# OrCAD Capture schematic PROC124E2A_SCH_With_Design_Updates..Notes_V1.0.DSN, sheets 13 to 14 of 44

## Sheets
13 09. USB TYPE-C POWER: size C; title: USB TYPE-C POWER
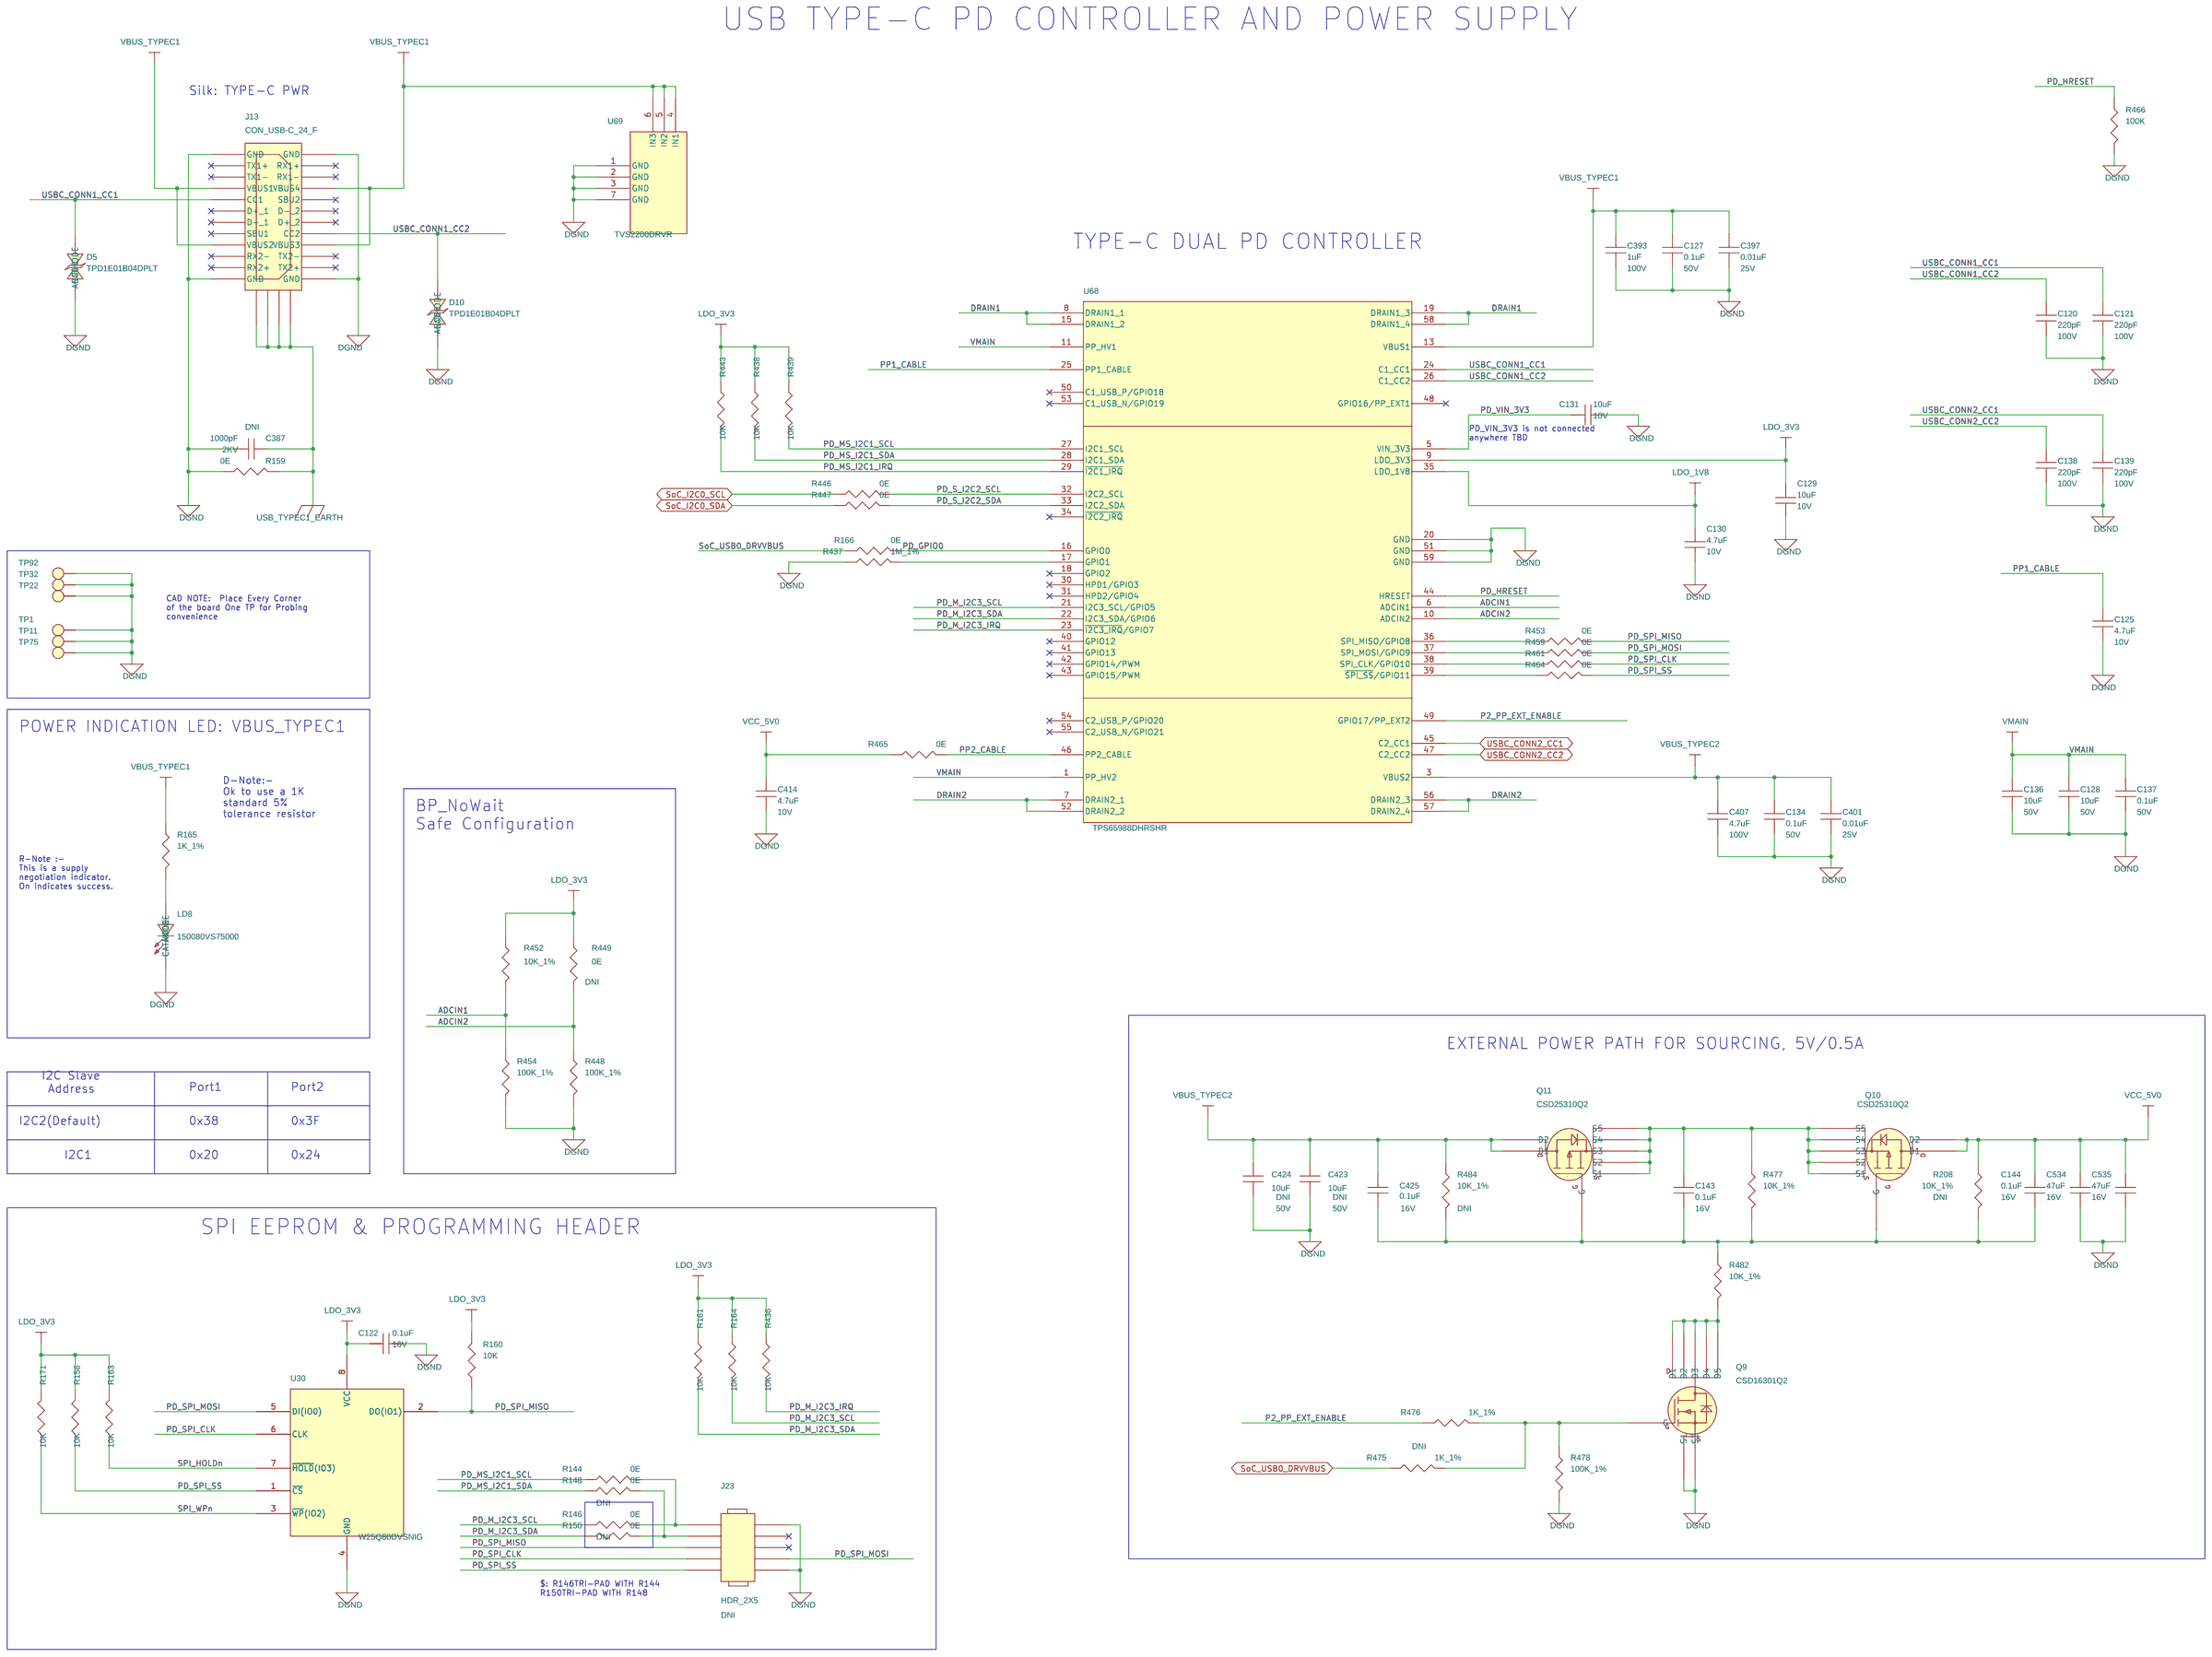
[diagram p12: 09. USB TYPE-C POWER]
14 10. PERIPHERAL POWER SUPPLY-1: size B; title: PERIPHERAL POWER SUPPLY -1
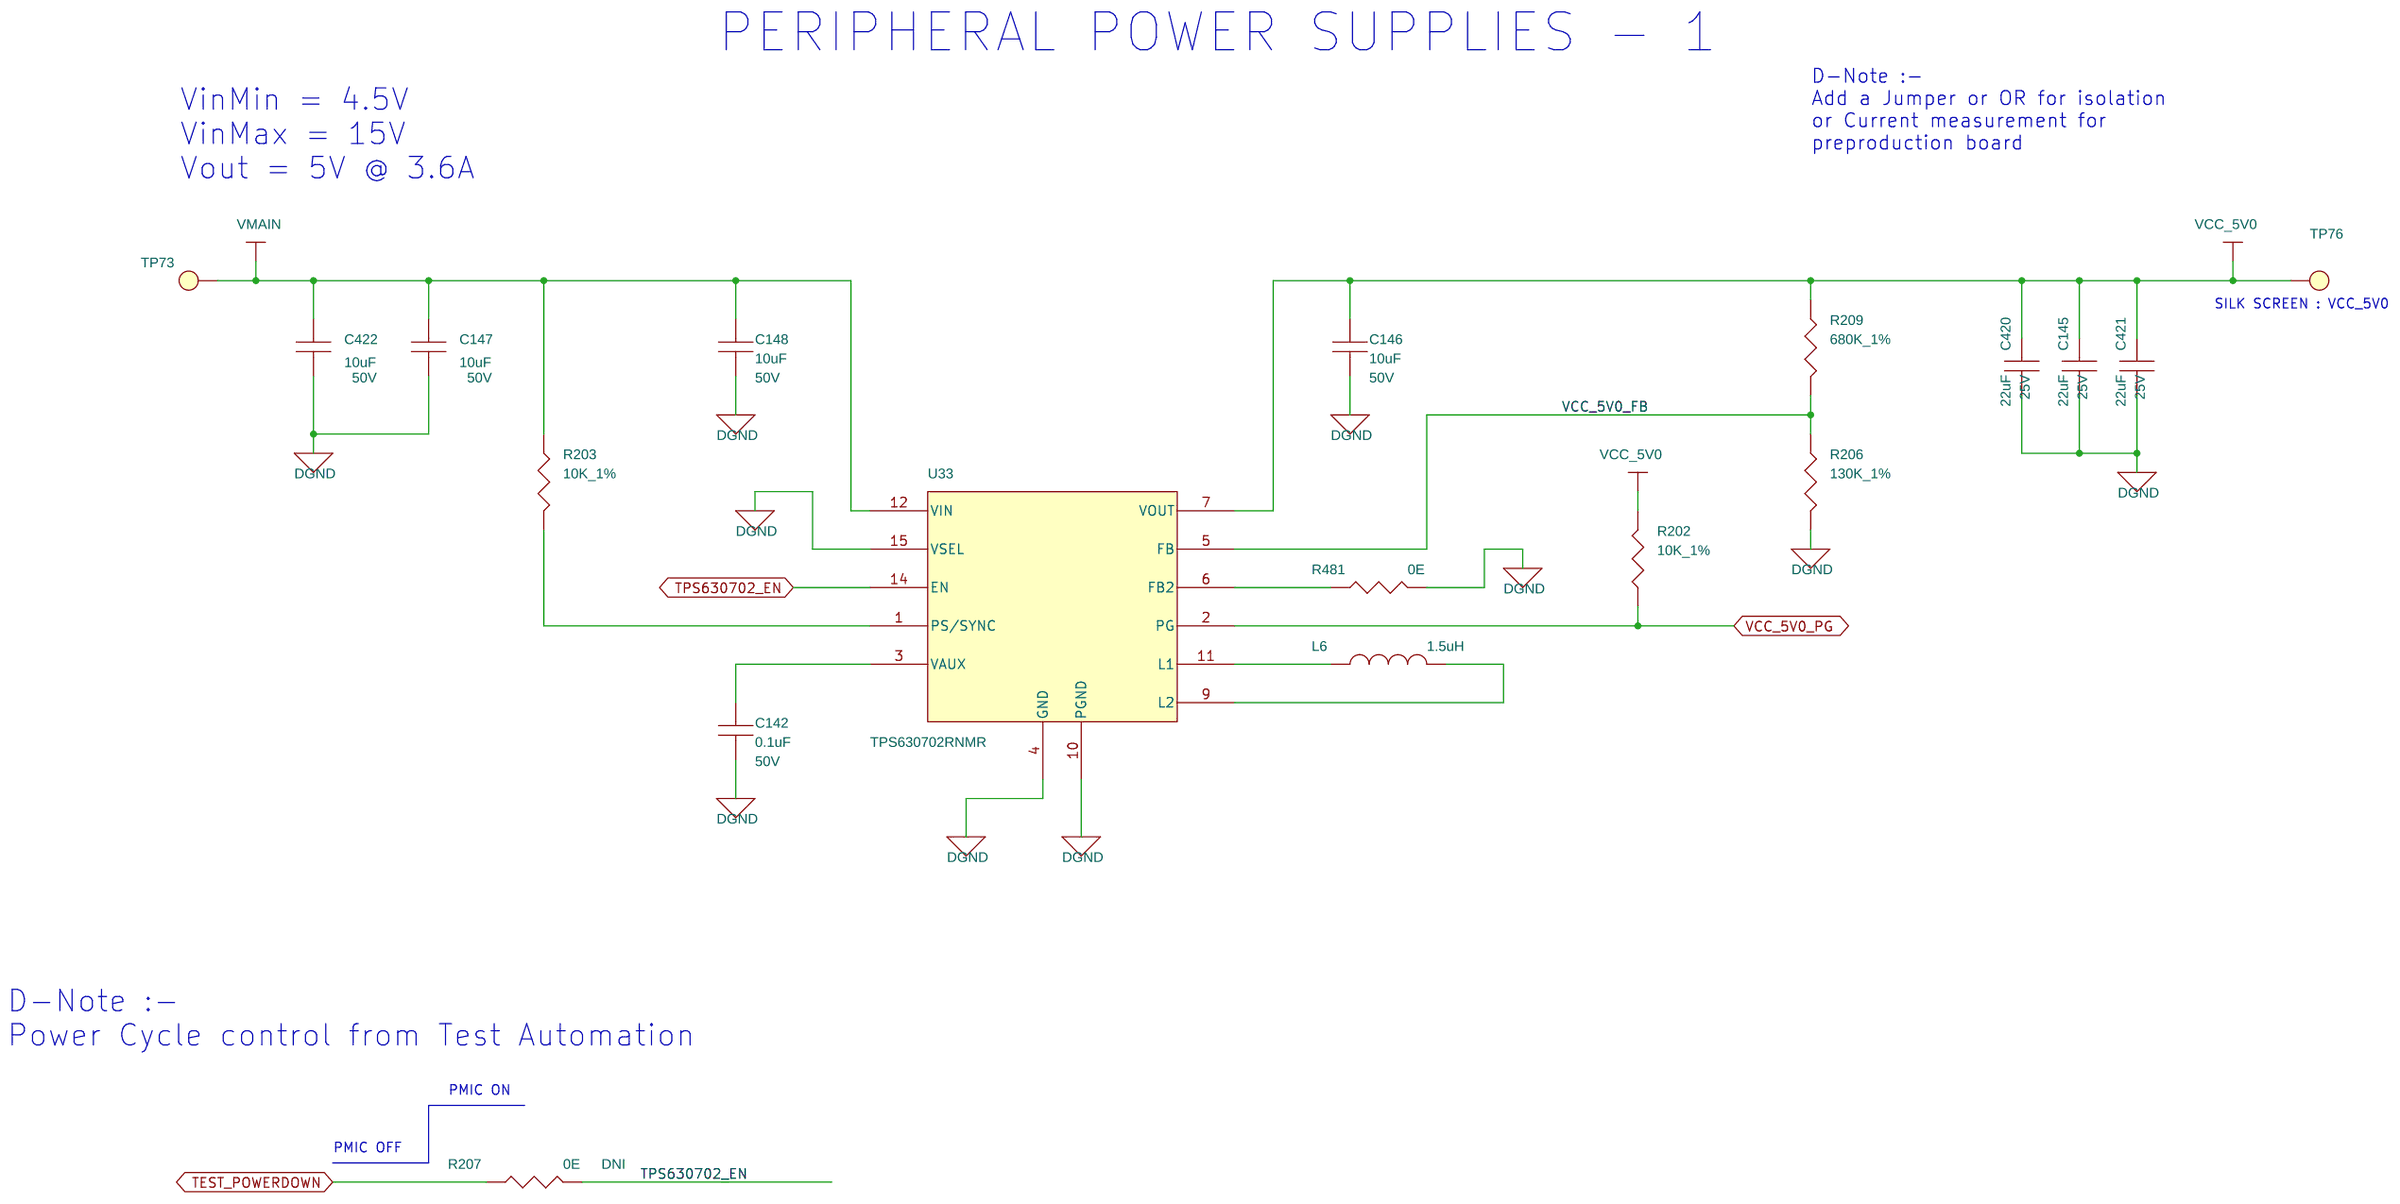
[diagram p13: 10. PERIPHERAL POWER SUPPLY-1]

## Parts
sheet 09. USB TYPE-C POWER
C120  220pF  [CAP0402_0-75]
C121  220pF  [CAP0402_0-75]
C122  0.1uF  [CAP0201_0-5]
C125  4.7uF  [CAP0402_0-75]
C127  0.1uF  [CAP0402_0-75]
C128  10uF  [CAP0805_1-5]
C129  10uF  [CAP0402_0-75]
C130  4.7uF  [CAP0402_0-75]
C131  10uF  [CAP0402_0-75]
C134  0.1uF  [CAP0402_0-75]
C136  10uF  [CAP0805_1-5]
C137  0.1uF  [CAP0402_0-75]
C138  220pF  [CAP0402_0-75]
C139  220pF  [CAP0402_0-75]
C143  0.1uF  [CAP0201_0-5]
C144  0.1uF  [CAP0201_0-5]
C387  1000pF  [CAP1206_1-75]
C393  1uF  [CAP0805_1-5]
C397  0.01uF  [CAP0201_0-5]
C401  0.01uF  [CAP0201_0-5]
C407  4.7uF  [CAP1206_2]
C414  4.7uF  [CAP0402_0-75]
C423  10uF  [CAP0805_1-5]
C424  10uF  [CAP0805_1-5]
C425  0.1uF  [CAP0201_0-5]
C534  47uF  [CAP1206_2]
C535  47uF  [CAP1206_2]
D5  TPD1E01B04DPLT  [DIO_DFN0201_0-4]
D10  TPD1E01B04DPLT  [DIO_DFN0201_0-4]
J13  CON_USB-C_24_F  [CON_USBC24_2012670_S_R_S_3-9]
J23  HDR_2X5  [HDR_2X5_PEC05DAAN_S_T_8-6]
LD8  150080VS75000  [LED_150080VS75000_80X50_SMD_0-8]
Q9  CSD16301Q2  [WSON6_CSD13202Q2_80X80_0-8]
Q10  CSD25310Q2  [SON6_CSD17313Q2_80X80]
Q11  CSD25310Q2  [SON6_CSD17313Q2_80X80]
R144  0E  [RES0201_0-5]
R146  0E  [RES0201_0-5]
R148  0E  [RES0201_0-5]
R150  0E  [RES0201_0-5]
R158  10K  [RES0201_0-5]
R159  0E  [RES0603_0-75]
R160  10K  [RES0201_0-5]
R161  10K  [RES0201_0-5]
R163  10K  [RES0201_0-5]
R164  10K  [RES0201_0-5]
R165  1K_1%  [RES0402_0-5]
R166  0E  [RES0402_0-5]
R171  10K  [RES0201_0-5]
R208  10K_1%  [RES0201_0-5]
R436  10K  [RES0201_0-5]
R437  1M_1%  [RES0402_0-5]
R438  10K  [RES0201_0-5]
R439  10K  [RES0201_0-5]
R443  10K  [RES0201_0-5]
R446  0E  [RES0201_0-5]
R447  0E  [RES0201_0-5]
R448  100K_1%  [RES0402_0-5]
R449  0E  [RES0201_0-5]
R452  10K_1%  [RES0201_0-5]
R453  0E  [RES0402_0-5]
R454  100K_1%  [RES0402_0-5]
R459  0E  [RES0402_0-5]
R461  0E  [RES0402_0-5]
R464  0E  [RES0402_0-5]
R465  0E  [RES0201_0-5]
R466  100K  [RES0201_0-5]
R475  1K_1%  [RES0201_0-5]
R476  1K_1%  [RES0201_0-5]
R477  10K_1%  [RES0201_0-5]
R478  100K_1%  [RES0402_0-5]
R482  10K_1%  [RES0201_0-5]
R484  10K_1%  [RES0201_0-5]
TP1  TP20_SMD  [TP20_SMD]
TP11  TP20_SMD  [TP20_SMD]
TP22  TP20_SMD  [TP20_SMD]
TP32  TP20_SMD  [TP20_SMD]
TP75  TP20_SMD  [TP20_SMD]
TP92  TP20_SMD  [TP20_SMD]
U30  W25Q80DVSNIG  [SOIC8_1-8]
U68  TPS65988DHRSHR  [VQFN56_TPS65987D_280X280_1]
U69  TVS2200DRVR  [SON6_25-59_85X85_0-8]
sheet 10. PERIPHERAL POWER SUPPLY-1
C142  0.1uF  [CAP0402_0-75]
C145  22uF  [CAP0805_1-5]
C146  10uF  [CAP0805_1-5]
C147  10uF  [CAP0805_1-5]
C148  10uF  [CAP0805_1-5]
C420  22uF  [CAP0805_1-5]
C421  22uF  [CAP0805_1-5]
C422  10uF  [CAP0805_1-5]
L6  1.5uH  [IND_XFL4020_170X170_SMD_2-1]
R202  10K_1%  [RES0201_0-5]
R203  10K_1%  [RES0201_0-5]
R206  130K_1%  [RES0402_0-5]
R207  0E  [RES0201_0-5]
R209  680K_1%  [RES0402_0-5]
R481  0E  [RES0201_0-5]
TP73  TP20_SMD  [TP20_SMD]
TP76  TP20_SMD  [TP20_SMD]
U33  TPS630702RNMR  [VQFNHR15_TPS630701_100X120_1]

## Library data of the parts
C120 C121 C138 C139 = CAP: CAP CERAMIC 220pF 100V 5% C0G(NP0) 0402; Chkd/date: MANIRAJA/061021; Crtd /date: ALVY/051021; Custom_Duty: 15%; Customs_HS_Code: 85322990; Distributor_name: DIGIKEY; Distributor_part_number: 490-GRM1555C2A221JE01DTR-ND; Footprint Path: Y:\MIS_DATABASE\Library\ALTIUM_TOOL\PCB_FOOTPRINTS\Altium_Footprint_Lib.PcbLib; Height: 0.55MM; Library Path: Y:\MIS_DATABASE\Library\ALTIUM_TOOL\SCHEMATICS_PARTS\MS_DISCRETE_Library.schlib; Mfr_name: MURATA; Mfr_part_number: GRM1555C2A221JE01D; Mistral Part No: 120021100001-R; Package: 0402; Part_type: CAPACITORS\CERAMIC; Project: TI_AM62x SKEVM_BRD; RoHS: RoHS; Temperature: -55°C+125°C; Tolerance: 5%; Voltage: 100V; Wattage: NA; Weight: 1.6mg; Datasheet: Y:\MIS_DATABASE\DATASHEETS\CAPACITORS\GRM1555C2A221JE01.PDF
C122 C143 C144 C425 = CAP: CAP CERAMIC 0.1uF 16V 10% X5R 0201; Chkd/date: MANIRAJA/230118; Crtd /date: MANIRAJA/230118; Custom_Duty: 15%; Customs_HS_Code: 85322990; Distributor_name: DIGIKEY; Distributor_part_number: 490-14305-1-ND; Footprint Path: Y:\MIS_DATABASE\Library\ALTIUM_TOOL\PCB_FOOTPRINTS\Altium_Footprint_Lib.PcbLib; Height: 0.33MM; Library Path: Y:\MIS_DATABASE\Library\ALTIUM_TOOL\SCHEMATICS_PARTS\MS_DISCRETE_Library.schlib; Mfr_name: MURATA; Mfr_part_number: GRM033R61C104KE14D; Mistral Part No: 120009030072-R; Package: 0201; Part_type: CAPACITORS\CERAMIC; Project: TI_MAXIE_CPB; RoHS: RoHS; Temperature: -55°C+85°C; Tolerance: 10%; Voltage: 16V; Wattage: NA; Weight: 0.33mg; Datasheet: Y:\MIS_DATABASE\DATASHEETS\CAPACITORS\GRM033R61C104KE14.PDF
C125 C130 C414 = CAP: CAP CERAMIC 4.7uF 10V 20% X5R 0402; Chkd/date: MANIRAJA/110718; Crtd /date: ALVY/110718; Custom_Duty: 15%; Customs_HS_Code: 85322990; Distributor_name: DIGIKEY; Distributor_part_number: 490-14306-1-ND; Footprint Path: Y:\MIS_DATABASE\Library\ALTIUM_TOOL\PCB_FOOTPRINTS\Altium_Footprint_Lib.PcbLib; Height: 0.65MM; Library Path: Y:\MIS_DATABASE\Library\ALTIUM_TOOL\SCHEMATICS_PARTS\MS_DISCRETE_Library.schlib; Mfr_name: MURATA; Mfr_part_number: GRM155R61A475MEAAD; Mistral Part No: 120012060002-R; Package: 0402; Part_type: CAPACITORS\CERAMIC; Project: TI_J7SVB_PCIE_ADD-ON-CARD; RoHS: RoHS; Temperature: -55°C+85°C; Tolerance: 20%; Voltage: 10V; Wattage: NA; Weight: 14mg; Datasheet: Y:\MIS_DATABASE\DATASHEETS\CAPACITORS\GRM155R61A475MEAAD.PDF
C127 C134 C137 C142 = CAP: CAP CERAMIC 0.1uF 50V 10% X7R 0402; Chkd/date: MANIRAJA/261020; Crtd /date: ALVY/211020; Custom_Duty: 15%; Customs_HS_Code: 85322990; Distributor_name: DIGIKEY; Distributor_part_number: 490-10700-1-ND; Footprint Path: Y:\MIS_DATABASE\Library\ALTIUM_TOOL\PCB_FOOTPRINTS\Altium_Footprint_Lib.PcbLib; Height: 0.55MM; Library Path: Y:\MIS_DATABASE\Library\ALTIUM_TOOL\SCHEMATICS_PARTS\MS_DISCRETE_Library.schlib; Mfr_name: MURATA; Mfr_part_number: GRM155R71H104KE14D; Mistral Part No: 120011100014-R; Package: 0402; Part_type: CAPACITORS\CERAMIC; Project: J7_CP; RoHS: RoHS; Temperature: -55°C+125°C; Tolerance: 10%; Voltage: 50V; Wattage: NA; Weight: 3.1mg; Datasheet: Y:\MIS_DATABASE\DATASHEETS\CAPACITORS\GRM155R71H104KE14.PDF
C128 C136 C146-C148 C422 = CAP: CAP CERAMIC 10uF 50V 10% X5R 0805; Chkd/date: MANIRAJA/010321; Crtd /date: ALVY/010321; Custom_Duty: 15%; Customs_HS_Code: 85322990; Distributor_name: DIGIKEY; Distributor_part_number: 490-18663-1-ND; Footprint Path: Y:\MIS_DATABASE\Library\ALTIUM_TOOL\PCB_FOOTPRINTS\Altium_Footprint_Lib.PcbLib; Height: 1.45MM; Library Path: Y:\MIS_DATABASE\Library\ALTIUM_TOOL\SCHEMATICS_PARTS\MS_DISCRETE_Library.schlib; Mfr_name: MURATA; Mfr_part_number: GRM21BR61H106KE43L; Mistral Part No: 120021030002-R; Package: 0805; Part_type: CAPACITORS\CERAMIC; Project: J7ES_SK_BRD; RoHS: RoHS; Temperature: -55°C+85°C; Tolerance: 10%; Voltage: 50V; Wattage: NA; Weight: 6.4mg; Datasheet: Y:\MIS_DATABASE\DATASHEETS\CAPACITORS\GRM21BR61H106KE43.PDF
C129 C131 = CAP: CAP CERAMIC 10uF 10V 20% X5R 0402; Chkd/date: MANIRAJA/300520; Crtd /date: ALVY/260520; Custom_Duty: 15%; Customs_HS_Code: 85322990; Distributor_name: DIGIKEY; Distributor_part_number: 490-GRM155R61A106ME11DTR-ND; Footprint Path: Y:\MIS_DATABASE\Library\ALTIUM_TOOL\PCB_FOOTPRINTS\Altium_Footprint_Lib.PcbLib; Height: 0.55MM; Library Path: Y:\MIS_DATABASE\Library\ALTIUM_TOOL\SCHEMATICS_PARTS\MS_DISCRETE_Library.schlib; Mfr_name: MURATA; Mfr_part_number: GRM155R61A106ME11D; Mistral Part No: 120013110019-R; Package: 0402; Part_type: CAPACITORS\CERAMIC; Project: QCS610_NANOSOM; RoHS: RoHS; Temperature: -55°C+85°C; Tolerance: 20%; Voltage: 10V; Wattage: NA; Weight: 3.1mg; Datasheet: Y:\MIS_DATABASE\DATASHEETS\CAPACITORS\MURATA-GXX-SER_NOV17.PDF
C387 = CAP: CAP CERAMIC 1000pF 2KV 10% X7R 1206; Assembly_Instruction: DNI; Chkd/date: SHREESHAIL/291106; Crtd /date: MAZHAR/281106; Custom_Duty: 15%; Customs_HS_Code: 85322990; Distributor_name: DIGIKEY; Distributor_part_number: 478-2956-1-ND; Footprint Path: Y:\MIS_DATABASE\Library\ALTIUM_TOOL\PCB_FOOTPRINTS\Altium_Footprint_Lib.PcbLib; Height: 1.52MM; Library Path: Y:\MIS_DATABASE\Library\ALTIUM_TOOL\SCHEMATICS_PARTS\MS_DISCRETE_Library.schlib; Mfr_name: AVX CORPORATION; Mfr_part_number: 1206GC102KAT1A; Mistral Part No: 120015080006-R; Package: 1206; Part_type: CAPACITORS\CERAMIC; Project: ADR1B; RoHS: RoHS; Temperature: -55°C+125°C; Tolerance: 10%; Voltage: 2KV; Wattage: NA; Weight: 16.2mg; Datasheet: Y:\MIS_DATABASE\DATASHEETS\CAPACITORS\AVX_HV-MLC.PDF
C393 = CAP: CAP CERAMIC 1uF 100V 10% X7S 0805; Chkd/date: MANIRAJA/160921; Crtd /date: ALVY/150921; Custom_Duty: 15%; Customs_HS_Code: 85322990; Distributor_name: DIGIKEY; Distributor_part_number: 490-14464-1-ND; Footprint Path: Y:\MIS_DATABASE\Library\ALTIUM_TOOL\PCB_FOOTPRINTS\Altium_Footprint_Lib.PcbLib; Height: 1.45MM; Library Path: Y:\MIS_DATABASE\Library\ALTIUM_TOOL\SCHEMATICS_PARTS\MS_DISCRETE_Library.schlib; Mfr_name: MURATA; Mfr_part_number: GRM21BC72A105KE01L; Mistral Part No: 120013030002-R; Package: 0805; Part_type: CAPACITORS\CERAMIC; Project: TI_AM62x SKEVM_BRD; RoHS: RoHS; Temperature: -55°C+125°C; Tolerance: 10%; Voltage: 100V; Wattage: NA; Weight: 6.4mg; Datasheet: Y:\MIS_DATABASE\DATASHEETS\CAPACITORS\GRM21BC72A105KE01.PDF
C397 C401 = CAP: CAP CERAMIC 0.01uF 25V 10% X5R 0201; Chkd/date: MANIRAJA/230118; Crtd /date: MANIRAJA/230118; Custom_Duty: 15%; Customs_HS_Code: 85322990; Distributor_name: DIGIKEY; Distributor_part_number: GRM033R61E103KA12J-ND; Footprint Path: Y:\MIS_DATABASE\Library\ALTIUM_TOOL\PCB_FOOTPRINTS\Altium_Footprint_Lib.PcbLib; Height: 0.33MM; Library Path: Y:\MIS_DATABASE\Library\ALTIUM_TOOL\SCHEMATICS_PARTS\MS_DISCRETE_Library.schlib; Mfr_name: MURATA; Mfr_part_number: GRM033R61E103KA12J; Mistral Part No: 120018010007-R; Package: 0201; Part_type: CAPACITORS\CERAMIC; Project: TI_MAXIE_CPB; RoHS: RoHS; Temperature: -55°C+85°C; Tolerance: 10%; Voltage: 25V; Wattage: NA; Weight: 0.33mg; Datasheet: Y:\MIS_DATABASE\DATASHEETS\CAPACITORS\GRM033R61E103KA12.PDF
C407 = CAP: CAP CERAMIC 4.7uF 100V 10% X7S 1206; Chkd/date: MANIRAJA/121020; Crtd /date: ALVY/091020; Custom_Duty: 15%; Customs_HS_Code: 85322990; Distributor_name: DIGIKEY; Distributor_part_number: 490-18620-1-ND; Footprint Path: Y:\MIS_DATABASE\Library\ALTIUM_TOOL\PCB_FOOTPRINTS\Altium_Footprint_Lib.PcbLib; Height: 1.90MM; Library Path: Y:\MIS_DATABASE\Library\ALTIUM_TOOL\SCHEMATICS_PARTS\MS_DISCRETE_Library.schlib; Mfr_name: MURATA; Mfr_part_number: GRM31CC72A475KE11L; Mistral Part No: 120020100021-R; Package: 1206; Part_type: CAPACITORS\CERAMIC; Project: ECU_RO; RoHS: RoHS; Temperature: -55°C+125°C; Tolerance: 10%; Voltage: 100V; Wattage: NA; Weight: 64mg; Datasheet: Y:\MIS_DATABASE\DATASHEETS\CAPACITORS\GRM31CC72A475KE11.PDF
C423 C424 = CAP: CAP CERAMIC 10uF 50V 10% X5R 0805; Assembly_Instruction: DNI; Chkd/date: MANIRAJA/010321; Crtd /date: ALVY/010321; Custom_Duty: 15%; Customs_HS_Code: 85322990; Distributor_name: DIGIKEY; Distributor_part_number: 490-18663-1-ND; Footprint Path: Y:\MIS_DATABASE\Library\ALTIUM_TOOL\PCB_FOOTPRINTS\Altium_Footprint_Lib.PcbLib; Height: 1.45MM; Library Path: Y:\MIS_DATABASE\Library\ALTIUM_TOOL\SCHEMATICS_PARTS\MS_DISCRETE_Library.schlib; Mfr_name: MURATA; Mfr_part_number: GRM21BR61H106KE43L; Mistral Part No: 120021030002-R; Package: 0805; Part_type: CAPACITORS\CERAMIC; Project: J7ES_SK_BRD; RoHS: RoHS; Temperature: -55°C+85°C; Tolerance: 10%; Voltage: 50V; Wattage: NA; Weight: 6.4mg; Datasheet: Y:\MIS_DATABASE\DATASHEETS\CAPACITORS\GRM21BR61H106KE43.PDF
C534 C535 = CAP: CAP CERAMIC 47uF 16V 20% X5R 1206; Chkd/date: MANIRAJA/120218; Crtd /date: MANIRAJA/120218; Custom_Duty: 15%; Customs_HS_Code: 85322990; Distributor_name: DIGIKEY; Distributor_part_number: 587-5425-1-ND; Footprint Path: Y:\MIS_DATABASE\Library\ALTIUM_TOOL\PCB_FOOTPRINTS\Altium_Footprint_Lib.PcbLib; Height: 1.90MM; Library Path: Y:\MIS_DATABASE\Library\ALTIUM_TOOL\SCHEMATICS_PARTS\MS_DISCRETE_Library.schlib; Mfr_name: TAIYO YUDEN; Mfr_part_number: EMK316BBJ476ML-T; Mistral Part No: 120011060001-R; Package: 1206; Part_type: CAPACITORS\CERAMIC; Project: FCD_VPX3-3UCC_BP; RoHS: RoHS; Temperature: -55°C+85°C; Tolerance: 20%; Voltage: 16V; Wattage: NA; Weight: 16.2mg; Datasheet: Y:\MIS_DATABASE\DATASHEETS\CAPACITORS\EMK316BBJ476ML.PDF
D5 D10 = DIODE_TVS_DUAL: DIODE 1CH ESD PROTECTION FOR USB TYPE-C AND THUNDERBOLT3 X2SON2; Chkd/date: MANIRAJA/230920; Crtd /date: ALVY/230920; Custom_Duty: 15%; Customs_HS_Code: 85412900; Distributor_name: DIGIKEY; Distributor_part_number: 296-44484-1-ND; Footprint Path: Y:\MIS_DATABASE\Library\ALTIUM_TOOL\PCB_FOOTPRINTS\Altium_Footprint_Lib.PcbLib; Height: 0.32MM; Library Path: Y:\MIS_DATABASE\Library\ALTIUM_TOOL\SCHEMATICS_PARTS\MS_DISCRETE_Library.schlib; Mfr_name: TEXAS INSTRUMENTS; Mistral Part No: 130020090037-R; Package: X2SON2; Part_type: DIODE\TVS; Project: AM64X_SKEVM; RoHS: RoHS; Temperature: -40°C+125°C; Tolerance: NA; Voltage: NA; Wattage: NA; Weight: 0.2mg; Datasheet: Y:\MIS_DATABASE\DATASHEETS\DISCRETES\DIODES\TPD1E01B04.PDF
J13 = CON_USB-C_24_1240183621: CON USB-C TYPE 24POS FEMALE RT SMD; Chkd/date: MANIRAJA/050618; Crtd /date: ALVY/040618; Custom_Duty: 24%; Customs_HS_Code: 85369090; Distributor_name: DIGIKEY; Distributor_part_number: WM17992CT-ND; Footprint Path: Y:\MIS_DATABASE\Library\ALTIUM_TOOL\PCB_FOOTPRINTS\Altium_Footprint_Lib.PcbLib; Height: 3.86MM; Library Path: Y:\MIS_DATABASE\Library\ALTIUM_TOOL\SCHEMATICS_PARTS\MS_CONNECTOR_Library.schlib; Mfr_name: MOLEX; Mfr_part_number: 2012670005; Mistral Part No: 150018060002-R; Package: SMD; Part_type: CONNECTOR\USB; Project: TI_J7SVB_USB_ADD-ON-CARD; RoHS: RoHS; Temperature: -40°C+105°C; Tolerance: NA; Voltage: NA; Wattage: NA; Weight: 0.686g; Datasheet: Y:\MIS_DATABASE\DATASHEETS\CONNECTORS\2012670X.PDF
J23 = HEADER_5X2: CON HDR 2X5 2.54MM PITCH ST TH; Assembly_Instruction: DNI; Chkd/date: MANIRAJA/060821; Crtd /date: ALVY/060821; Custom_Duty: 24%; Customs_HS_Code: 85369090; Distributor_name: DIGIKEY; Distributor_part_number: S2012E-05-ND; Footprint Path: Y:\MIS_DATABASE\Library\ALTIUM_TOOL\PCB_FOOTPRINTS\Altium_Footprint_Lib.PcbLib; Height: 8.58MM; Library Path: Y:\MIS_DATABASE\Library\ALTIUM_TOOL\SCHEMATICS_PARTS\MS_CONNECTOR_Library.schlib; Mfr_name: SULLINS CONNECTOR; Mfr_part_number: PEC05DAAN; Mistral Part No: 150021080010-R; Package: THRU-HOLE; Part_type: CONNECTOR\HEADERS; Project: TI_AM335x SK_BRD; RoHS: RoHS; Temperature: -65°C+125°C; Tolerance: NA; Voltage: NA; Wattage: NA; Weight: NA; Datasheet: Y:\MIS_DATABASE\DATASHEETS\CONNECTORS\XXCXXDXXN.PDF
LD8 = DIODE_LED: DIODE LED BRIGHT GREEN SMD; Chkd/date: MANIRAJA/180820; Crtd /date: ALVY/180820; Custom_Duty: 24%; Customs_HS_Code: 85439000; Distributor_name: DIGIKEY; Distributor_part_number: 732-4986-1-ND; Footprint Path: Y:\MIS_DATABASE\Library\ALTIUM_TOOL\PCB_FOOTPRINTS\Altium_Footprint_Lib.PcbLib; Height: 0.80MM; Library Path: Y:\MIS_DATABASE\Library\ALTIUM_TOOL\SCHEMATICS_PARTS\MS_OPTO_Library.schlib; Mfr_name: WURTH ELECTRONICS; Mistral Part No: 130020080012-R; Package: SMD; Part_type: OPTO\LED; Project: AM64x_EVM_BRD; RoHS: RoHS; Temperature: -40°C+85°C; Tolerance: NA; Voltage: NA; Wattage: NA; Weight: 10mg; Datasheet: Y:\MIS_DATABASE\DATASHEETS\DISCRETES\LEDS\150080VS75000.PDF
Q9 = MOSFET_CSD17313Q2: IC MOSFET N-CHANNEL NEXFET 25V WSON6; Chkd/date: ALVY/071220; Crtd /date: MANIRAJA/071220; Custom_Duty: 15%; Customs_HS_Code: 85423100; Distributor_name: DIGIKEY; Distributor_part_number: 296-25260-1-ND; Footprint Path: Y:\MIS_DATABASE\Library\ALTIUM_TOOL\PCB_FOOTPRINTS\Altium_Footprint_Lib.PcbLib; Height: 0.80MM; Library Path: Y:\MIS_DATABASE\Library\ALTIUM_TOOL\SCHEMATICS_PARTS\MS_MOSFET_Library.schlib; Manufacturer: TEXAS INSTRUMENTS; Mfr_name: TEXAS INSTRUMENTS; Mistral Part No: 142020120008-R; Package: WSON6; Part_type: ICS\POWER\MOSFET; Project: TI_AM243x LP EVM; RoHS: RoHS; Temperature: -55°C+150°C; Tolerance: NA; Voltage: NA; Wattage: NA; Weight: 8.7mg; Datasheet: Y:\MIS_DATABASE\DATASHEETS\ICS\POWER\CSD16301Q2.PDF
Q10 Q11 = MOSFET_CSD25310Q2: IC MOSFET P-CHANNEL WSON6; Chkd/date: VASANTHA/191215; Crtd /date: VASANTHA/191215; Custom_Duty: 15%; Customs_HS_Code: 85423100; Distributor_name: DIGIKEY; Distributor_part_number: 296-38915-1-ND; Height: 0.85MM; Mfr_name: TEXAS INSTRUMENTS; Mistral Part No: 142015120011-R; Package: WSON6; Part_type: ICS\POWER\MOSFET; Project: DUET BOARD; RoHS: RoHS; Temperature: -55°C+150°C; Tolerance: NA; Voltage: NA; Wattage: NA; Weight: NA; Datasheet: Y:\MIS_DATABASE\DATASHEETS\DISCRETES\TRANSISTORS_FETS\CSD25310Q2.PDF
R144 R148 R446 R447 R481 = RESISTOR: RES 0E 1/20W 5% 0201; Chkd/date: NAVEED/301214; Crtd /date: MUDDU/120710; Custom_Duty: 15%; Customs_HS_Code: 85332119; Distributor_name: DIGIKEY; Distributor_part_number: 311-0.0NCT-ND; Footprint Path: Y:\MIS_DATABASE\Library\ALTIUM_TOOL\PCB_FOOTPRINTS\Altium_Footprint_Lib.PcbLib; Height: 0.26MM; Library Path: Y:\MIS_DATABASE\Library\ALTIUM_TOOL\SCHEMATICS_PARTS\MS_DISCRETE_Library.schlib; Mfr_name: YAGEO AMERICA; Mfr_part_number: RC0201JR-070RL; Mistral Part No: 110010070067-R; Package: 0201; Part_type: RESISTORS\FIXED; Project: PB_BUGBASE; RoHS: RoHS; Temperature: -55°C+125°C; Tolerance: 5%; Voltage: NA; Wattage: 1/20W; Weight: 0.17mg; Datasheet: Y:\MIS_DATABASE\DATASHEETS\RESISTORS\RCXXXXL-SER_MAR18.PDF
R146 R150 R207 = RESISTOR: RES 0E 1/20W 5% 0201; Assembly_Instruction: DNI; Chkd/date: NAVEED/301214; Crtd /date: MUDDU/120710; Custom_Duty: 15%; Customs_HS_Code: 85332119; Distributor_name: DIGIKEY; Distributor_part_number: 311-0.0NCT-ND; Footprint Path: Y:\MIS_DATABASE\Library\ALTIUM_TOOL\PCB_FOOTPRINTS\Altium_Footprint_Lib.PcbLib; Height: 0.26MM; Library Path: Y:\MIS_DATABASE\Library\ALTIUM_TOOL\SCHEMATICS_PARTS\MS_DISCRETE_Library.schlib; Mfr_name: YAGEO AMERICA; Mfr_part_number: RC0201JR-070RL; Mistral Part No: 110010070067-R; Package: 0201; Part_type: RESISTORS\FIXED; Project: PB_BUGBASE; RoHS: RoHS; Temperature: -55°C+125°C; Tolerance: 5%; Voltage: NA; Wattage: 1/20W; Weight: 0.17mg; Datasheet: Y:\MIS_DATABASE\DATASHEETS\RESISTORS\RCXXXXL-SER_MAR18.PDF
R158 R160 R161 R163 R164 R171 R436 R438 R439 R443 = RESISTOR: RES 10K 1/20W 5% 0201; Chkd/date: MANIRAJA/050517; Crtd /date: MANIRAJA/050517; Custom_Duty: 15%; Customs_HS_Code: 85332119; Distributor_name: DIGIKEY; Distributor_part_number: 311-10KNCT-ND; Footprint Path: Y:\MIS_DATABASE\Library\ALTIUM_TOOL\PCB_FOOTPRINTS\Altium_Footprint_Lib.PcbLib; Height: 0.26MM; Library Path: Y:\MIS_DATABASE\Library\ALTIUM_TOOL\SCHEMATICS_PARTS\MS_DISCRETE_Library.schlib; Mfr_name: YAGEO AMERICA; Mfr_part_number: RC0201JR-0710KL; Mistral Part No: 110010070051-R; Package: 0201; Part_type: RESISTORS\FIXED; Project: GOLDEN-I LITE; RoHS: RoHS; Temperature: -55°C+125°C; Tolerance: 5%; Voltage: NA; Wattage: 1/20W; Weight: 0.17mg; Datasheet: Y:\MIS_DATABASE\DATASHEETS\RESISTORS\RCXXXXL-SER_MAR18.PDF
R159 = RESISTOR: RES 0E 1/10W 5% 0603; Chkd/date: MANIRAJA/051217; Crtd /date: BAVISH/180211; Custom_Duty: 15%; Customs_HS_Code: 85332119; Distributor_name: DIGIKEY; Distributor_part_number: 311-0.0GRCT-ND; Footprint Path: Y:\MIS_DATABASE\Library\ALTIUM_TOOL\PCB_FOOTPRINTS\Altium_Footprint_Lib.PcbLib; Height: 0.55MM; Library Path: Y:\MIS_DATABASE\Library\ALTIUM_TOOL\SCHEMATICS_PARTS\MS_DISCRETE_Library.schlib; Mfr_name: YAGEO AMERICA; Mfr_part_number: RC0603JR-070RL; Mistral Part No: 110011020013-R; Package: 0603; Part_type: RESISTORS\FIXED; Project: KENNEL; RoHS: RoHS; Temperature: -55°C+155°C; Tolerance: 5%; Voltage: NA; Wattage: 1/10W; Weight: 2mg; Datasheet: Y:\MIS_DATABASE\DATASHEETS\RESISTORS\RCXXXXL-SER_MAR18.PDF
R165 = RESISTOR: RES 1K 1/10W 1% 0402; Chkd/date: VASANTHA/281216; Crtd /date: MAZHAR/150506; Custom_Duty: 15%; Customs_HS_Code: 85332119; Distributor_name: DIGIKEY; Distributor_part_number: P1.00KLCT-ND; Footprint Path: Y:\MIS_DATABASE\Library\ALTIUM_TOOL\PCB_FOOTPRINTS\Altium_Footprint_Lib.PcbLib; Height: 0.40MM; Library Path: Y:\MIS_DATABASE\Library\ALTIUM_TOOL\SCHEMATICS_PARTS\MS_DISCRETE_Library.schlib; Mfr_name: PANASONIC-ECG; Mfr_part_number: ERJ-2RKF1001X; Mistral Part No: 110009030411-R; Package: 0402; Part_type: RESISTORS\FIXED; Project: VOCERA; RoHS: RoHS; Temperature: -55°C+155°C; Tolerance: 1%; Voltage: NA; Wattage: 1/10W; Weight: 0.8mg; Datasheet: Y:\MIS_DATABASE\DATASHEETS\RESISTORS\PAN-ERJSER_NOV17.PDF
R166 R453 R459 R461 R464 = RESISTOR: RES 0E 1/16W JUMPER 0402; Chkd/date: VASANTHA/201216; Crtd /date: MUDDU/190810; Custom_Duty: 15%; Customs_HS_Code: 85332119; Distributor_name: DIGIKEY; Distributor_part_number: 541-0.0JCT-ND; Footprint Path: Y:\MIS_DATABASE\Library\ALTIUM_TOOL\PCB_FOOTPRINTS\Altium_Footprint_Lib.PcbLib; Height: 0.40MM; Library Path: Y:\MIS_DATABASE\Library\ALTIUM_TOOL\SCHEMATICS_PARTS\MS_DISCRETE_Library.schlib; Mfr_name: VISHAY; Mfr_part_number: CRCW04020000Z0ED; Mistral Part No: 110010080019-R; Package: 0402; Part_type: RESISTORS\FIXED; Project: PB_BUGBASE; RoHS: RoHS; Temperature: -55°C+155°C; Tolerance: NA; Voltage: NA; Wattage: 1/16W; Weight: 0.65mg; Datasheet: Y:\MIS_DATABASE\DATASHEETS\RESISTORS\CRCW0603.PDF
R208 R484 = RESISTOR: RES 10K 1/20W 1% 0201; Assembly_Instruction: DNI; Chkd/date: MANIRAJA/260618; Crtd /date: ALVY/260618; Custom_Duty: 15%; Customs_HS_Code: 85332119; Distributor_name: DIGIKEY; Distributor_part_number: 541-10.0KABCT-ND; Footprint Path: Y:\MIS_DATABASE\Library\ALTIUM_TOOL\PCB_FOOTPRINTS\Altium_Footprint_Lib.PcbLib; Height: 0.28MM; Library Path: Y:\MIS_DATABASE\Library\ALTIUM_TOOL\SCHEMATICS_PARTS\MS_DISCRETE_Library.schlib; Mfr_name: VISHAY; Mfr_part_number: CRCW020110K0FNED; Mistral Part No: 110018060032-R; Package: 0201; Part_type: RESISTORS\FIXED; Project: NEXTNAV_LPRX_BOARD; RoHS: RoHS; Temperature: -55°C+155°C; Tolerance: 1%; Voltage: NA; Wattage: 1/20W; Weight: 0.17mg; Datasheet: Y:\MIS_DATABASE\DATASHEETS\RESISTORS\CRCW0201.PDF
R437 = RESISTOR: RES 1M 1/16W 1% 0402; Chkd/date: MANIRAJA/190319; Crtd /date: MANIRAJA/190319; Custom_Duty: 15%; Customs_HS_Code: 85332119; Distributor_name: DIGIKEY; Distributor_part_number: 311-1.00MLRCT-ND; Footprint Path: Y:\MIS_DATABASE\Library\ALTIUM_TOOL\PCB_FOOTPRINTS\Altium_Footprint_Lib.PcbLib; Height: 0.40MM; Library Path: Y:\MIS_DATABASE\Library\ALTIUM_TOOL\SCHEMATICS_PARTS\MS_DISCRETE_Library.schlib; Mfr_name: YAGEO AMERICA; Mfr_part_number: RC0402FR-071ML; Mistral Part No: 110014060045-R; Package: 0402; Part_type: RESISTORS\FIXED; Project: G4SLIM; RoHS: RoHS; Temperature: -55°C+155°C; Tolerance: 1%; Voltage: NA; Wattage: 1/16W; Weight: 0.65mg; Datasheet: Y:\MIS_DATABASE\DATASHEETS\RESISTORS\RCXXXXL-SER_MAR18.PDF
R448 R454 R478 = RESISTOR: RES 100K 1/10W 1% 0402; Chkd/date: VASANTHA/201216; Crtd /date: MAZHAR/130306; Custom_Duty: 15%; Customs_HS_Code: 85332119; Distributor_name: DIGIKEY; Distributor_part_number: P100KLCT-ND; Footprint Path: Y:\MIS_DATABASE\Library\ALTIUM_TOOL\PCB_FOOTPRINTS\Altium_Footprint_Lib.PcbLib; Height: 0.40MM; Library Path: Y:\MIS_DATABASE\Library\ALTIUM_TOOL\SCHEMATICS_PARTS\MS_DISCRETE_Library.schlib; Mfr_name: PANASONIC-ECG; Mfr_part_number: ERJ-2RKF1003X; Mistral Part No: 110009030187-R; Package: 0402; Part_type: RESISTORS\FIXED; Project: J32; RoHS: RoHS; Temperature: -55°C+155°C; Tolerance: 1%; Voltage: NA; Wattage: 1/10W; Weight: 0.8mg; Datasheet: Y:\MIS_DATABASE\DATASHEETS\RESISTORS\PAN-ERJSER_NOV17.PDF
R449 = RESISTOR: RES 0E 1/20W JUMPER 0201; Assembly_Instruction: DNI; Chkd/date: MANIRAJA/290421; Crtd /date: ALVY/290421; Custom_Duty: 15%; Customs_HS_Code: 85332119; Distributor_name: DIGIKEY; Distributor_part_number: P15979CT-ND; Footprint Path: Y:\MIS_DATABASE\Library\ALTIUM_TOOL\PCB_FOOTPRINTS\Altium_Footprint_Lib.PcbLib; Height: 0.26MM; Library Path: Y:\MIS_DATABASE\Library\ALTIUM_TOOL\SCHEMATICS_PARTS\MS_DISCRETE_Library.schlib; Mfr_name: PANASONIC-ECG; Mfr_part_number: ERJ-1GN0R00C; Mistral Part No: 110009030078-R; Package: 0201; Part_type: RESISTORS\FIXED; Project: SRMS-SAR_BRD; RoHS: RoHS; Temperature: -55°C+125°C; Tolerance: NA; Voltage: NA; Wattage: 1/20W; Weight: 0.15mg; Datasheet: Y:\MIS_DATABASE\DATASHEETS\RESISTORS\PAN-ERJSER_NOV17.PDF
R452 = RESISTOR: RES 10K 1/20W 1% 0201; Chkd/date: VASANTHA/270117; Crtd /date: MANIRAJA/270117; Custom_Duty: 15%; Customs_HS_Code: 85332119; Distributor_name: DIGIKEY; Distributor_part_number: 311-10.0KMCT-ND; Footprint Path: Y:\MIS_DATABASE\Library\ALTIUM_TOOL\PCB_FOOTPRINTS\Altium_Footprint_Lib.PcbLib; Height: 0.26MM; Library Path: Y:\MIS_DATABASE\Library\ALTIUM_TOOL\SCHEMATICS_PARTS\MS_DISCRETE_Library.schlib; Manufacturer: YAGEO AMERICA; Mfr_name: YAGEO AMERICA; Mfr_part_number: RC0201FR-0710KL; Mistral Part No: 110011040018-R; Package: 0201; Part_type: RESISTORS\FIXED; Project: GOLDEN-I LITE; RoHS: RoHS; Temperature: -55°C+125°C; Tolerance: 1%; Voltage: NA; Wattage: 1/20W; Weight: 0.17mg; Datasheet: Y:\MIS_DATABASE\DATASHEETS\RESISTORS\RCXXXXL-SER_MAR18.PDF
R465 = RESISTOR: RES 0E 1/20W JUMPER 0201; Chkd/date: MANIRAJA/290421; Crtd /date: ALVY/290421; Custom_Duty: 15%; Customs_HS_Code: 85332119; Distributor_name: DIGIKEY; Distributor_part_number: P15979CT-ND; Footprint Path: Y:\MIS_DATABASE\Library\ALTIUM_TOOL\PCB_FOOTPRINTS\Altium_Footprint_Lib.PcbLib; Height: 0.26MM; Library Path: Y:\MIS_DATABASE\Library\ALTIUM_TOOL\SCHEMATICS_PARTS\MS_DISCRETE_Library.schlib; Mfr_name: PANASONIC-ECG; Mfr_part_number: ERJ-1GN0R00C; Mistral Part No: 110009030078-R; Package: 0201; Part_type: RESISTORS\FIXED; Project: SRMS-SAR_BRD; RoHS: RoHS; Temperature: -55°C+125°C; Tolerance: NA; Voltage: NA; Wattage: 1/20W; Weight: 0.15mg; Datasheet: Y:\MIS_DATABASE\DATASHEETS\RESISTORS\PAN-ERJSER_NOV17.PDF
R466 = RESISTOR: RES 100K 1/20W 5% 0201; Chkd/date: PRAVEEN/080922; Crtd /date: TAMILARASU/080922; Custom_Duty: 15%; Customs_HS_Code: 85332119; Distributor_name: DIGIKEY; Distributor_part_number: P123223CT-ND; Footprint Path: Y:\MIS_DATABASE\Library\ALTIUM_TOOL\PCB_FOOTPRINTS\Altium_Footprint_Lib.PcbLib; Height: 0.26MM; Library Path: Y:\MIS_DATABASE\Library\ALTIUM_TOOL\SCHEMATICS_PARTS\MS_DISCRETE_Library.schlib; Mfr_name: PANASONIC-ECG; Mfr_part_number: ERJ-1GNJ104C; Mistral Part No: 110022090005-R; Package: 0201; Part_type: RESISTORS\FIXED; Project: SK AM62Q LP EVM BRD; RoHS: RoHS; Temperature: -55°C+125°C; Tolerance: 5%; Voltage: NA; Wattage: 1/20W; Weight: 0.15mg; Datasheet: Y:\MIS_DATABASE\DATASHEETS\RESISTORS\PAN-ERJSER_NOV17.PDF
R475 = RESISTOR: RES 1K 1/20W 1% 0201; Assembly_Instruction: DNI; Chkd/date: JEBRAN/110815; Crtd /date: JEBRAN/110815; Custom_Duty: 15%; Customs_HS_Code: 85332119; Distributor_name: DIGIKEY; Distributor_part_number: 541-1.00KAABCT-ND; Footprint Path: Y:\MIS_DATABASE\Library\ALTIUM_TOOL\PCB_FOOTPRINTS\Altium_Footprint_Lib.PcbLib; Height: 0.28MM; Library Path: Y:\MIS_DATABASE\Library\ALTIUM_TOOL\SCHEMATICS_PARTS\MS_DISCRETE_Library.schlib; Mfr_name: VISHAY; Mfr_part_number: CRCW02011K00FKED; Mistral Part No: 110015080014-R; Package: 0201; Part_type: RESISTORS\FIXED; Project: OCTASIC_3000; RoHS: RoHS; Temperature: -55°C+155°C; Tolerance: 1%; Voltage: NA; Wattage: 1/20W; Weight: 0.17mg; Datasheet: Y:\MIS_DATABASE\DATASHEETS\RESISTORS\CRCW0201.PDF
R476 = RESISTOR: RES 1K 1/20W 1% 0201; Chkd/date: JEBRAN/110815; Crtd /date: JEBRAN/110815; Custom_Duty: 15%; Customs_HS_Code: 85332119; Distributor_name: DIGIKEY; Distributor_part_number: 541-1.00KAABCT-ND; Footprint Path: Y:\MIS_DATABASE\Library\ALTIUM_TOOL\PCB_FOOTPRINTS\Altium_Footprint_Lib.PcbLib; Height: 0.28MM; Library Path: Y:\MIS_DATABASE\Library\ALTIUM_TOOL\SCHEMATICS_PARTS\MS_DISCRETE_Library.schlib; Mfr_name: VISHAY; Mfr_part_number: CRCW02011K00FKED; Mistral Part No: 110015080014-R; Package: 0201; Part_type: RESISTORS\FIXED; Project: OCTASIC_3000; RoHS: RoHS; Temperature: -55°C+155°C; Tolerance: 1%; Voltage: NA; Wattage: 1/20W; Weight: 0.17mg; Datasheet: Y:\MIS_DATABASE\DATASHEETS\RESISTORS\CRCW0201.PDF
R202 R203 R477 R482 = RESISTOR: RES 10K 1/20W 1% 0201; Chkd/date: VASANTHA/270117; Crtd /date: MANIRAJA/270117; Custom_Duty: 15%; Customs_HS_Code: 85332119; Distributor_name: DIGIKEY; Distributor_part_number: 311-10.0KMCT-ND; Footprint Path: Y:\MIS_DATABASE\Library\ALTIUM_TOOL\PCB_FOOTPRINTS\Altium_Footprint_Lib.PcbLib; Height: 0.26MM; Library Path: Y:\MIS_DATABASE\Library\ALTIUM_TOOL\SCHEMATICS_PARTS\MS_DISCRETE_Library.schlib; Mfr_name: YAGEO AMERICA; Mfr_part_number: RC0201FR-0710KL; Mistral Part No: 110011040018-R; Package: 0201; Part_type: RESISTORS\FIXED; Project: GOLDEN-I LITE; RoHS: RoHS; Temperature: -55°C+125°C; Tolerance: 1%; Voltage: NA; Wattage: 1/20W; Weight: 0.17mg; Datasheet: Y:\MIS_DATABASE\DATASHEETS\RESISTORS\RCXXXXL-SER_MAR18.PDF
TP1 TP11 TP22 TP32 TP75 TP92 = TESTPOINT: TESTPOINT CIR 20 SMD; Chkd/date: SHREESHAIL/171006; Crtd /date: MAZHAR/171006; Custom_Duty: NA; Customs_HS_Code: NA; Distributor_name: NA; Distributor_part_number: NA; Footprint Path: Y:\MIS_DATABASE\Library\ALTIUM_TOOL\PCB_FOOTPRINTS\Altium_Footprint_Lib.PcbLib; Height: NA; Library Path: Y:\MIS_DATABASE\Library\ALTIUM_TOOL\SCHEMATICS_PARTS\MS_DISCRETE_Library.schlib; MECHANICAL 3D STEP FILE: NA; Manufacturer: LOCAL; Mfr_name: LOCAL; Mistral Part No: NA; Package: SMD; Project: BT MODULE_CSRBC04; RoHS: NA; Temperature: NA; Tolerance: NA; Voltage: NA; Wattage: NA; Weight: NA; Datasheet: NA
U30 = W25Q80BWSNIG_SOIC8: IC SERIAL FLASH MEMORY SOIC8; Chkd/date: VASANTHA/150217; Crtd /date: MANIRAJA/150217; Custom_Duty: 15%; Customs_HS_Code: 85423100; Distributor_name: DIGIKEY; Distributor_part_number: W25Q80DVSNIG CT-ND; Height: 1.75MM; Mfr_name: WINBOND; Mfr_part_number: W25Q80DVSNIG-TR; Mistral Part No: 141117020010-R; Package: SOIC8; Part_type: ICS\DIGITAL\MEMORY; Project: SD820_NANO_SOM; RoHS: RoHS; Temperature: -40°C+85°C; Tolerance: NA; Voltage: NA; Wattage: NA; Weight: NA; Datasheet: Y:\MIS_DATABASE\DATASHEETS\ICS\MEMORY\W25Q80DVSS.PDF
U68 = TPS65988DJ_VQFN56: IC 2-PORT USB TYPE-C AND USB PD CONTROLLER WITH INTEGRATED POWER SWITCH VQFN56; Chkd/date: MANIRAJA/290721; Crtd /date: ALVY/280721; Custom_Duty: 15%; Customs_HS_Code: 85423100; Distributor_name: DIGIKEY; Distributor_part_number: 296-52068-1-ND; Footprint Path: Y:\MIS_DATABASE\Library\ALTIUM_TOOL\PCB_FOOTPRINTS\Altium_Footprint_Lib.PcbLib; Height: 1.00MM; Library Path: Y:\MIS_DATABASE\Library\ALTIUM_TOOL\SCHEMATICS_PARTS\MS_MISCPOWER_Library.schlib; Mfr_name: TEXAS INSTRUMENTS; Mistral Part No: 142021070017-R; Package: VQFN56; Part_type: ICS\POWER\MANAGEMENT; Project: TI_AM62x_SKEVM; RoHS: RoHS; Temperature: -10°C+75°C; Tolerance: NA; Voltage: NA; Wattage: NA; Weight: 127.6mg; Datasheet: Y:\MIS_DATABASE\DATASHEETS\ICS\POWER\TPS65988DHRSHR.PDF
U69 = TVS2200_WSON6: IC 22V FLAT-CLAMP SURGE PROTECTION DEVICE WSON6; Chkd/date: MANIRAJA/011021; Crtd /date: ALVY/011021; Custom_Duty: 15%; Customs_HS_Code: 85423100; Distributor_name: DIGIKEY; Distributor_part_number: 296-52187-1-ND; Footprint Path: Y:\MIS_DATABASE\Library\ALTIUM_TOOL\PCB_FOOTPRINTS\Altium_Footprint_Lib.PcbLib; Height: 0.80MM; Library Path: Y:\MIS_DATABASE\Library\ALTIUM_TOOL\SCHEMATICS_PARTS\MS_MISCPOWER_Library.schlib; Mfr_name: TEXAS INSTRUMENTS; Mistral Part No: 142021100001-R; Package: WSON6; Part_type: ICS\POWER; Project: TI_AM62x SKEVM_BRD; RoHS: RoHS; Temperature: -40°C+125°C; Tolerance: NA; Voltage: NA; Wattage: NA; Weight: 12mg; Datasheet: Y:\MIS_DATABASE\DATASHEETS\ICS\POWER\TVS2200.PDF
C145 C420 C421 = CAP: CAP CERAMIC 22uF 25V 20% X5R 0805; Chkd/date: MANIRAJA/110718; Crtd /date: ALVY/110718; Custom_Duty: 15%; Customs_HS_Code: 85322990; Distributor_name: DIGIKEY; Distributor_part_number: 490-14661-1-ND; Footprint Path: Y:\MIS_DATABASE\Library\ALTIUM_TOOL\PCB_FOOTPRINTS\Altium_Footprint_Lib.PcbLib; Height: 1.45MM; Library Path: Y:\MIS_DATABASE\Library\ALTIUM_TOOL\SCHEMATICS_PARTS\MS_DISCRETE_Library.schlib; Mfr_name: MURATA; Mfr_part_number: GRM21BR61E226ME44K; Mistral Part No: 120013120018-R; Package: 0805; Part_type: CAPACITORS\CERAMIC; Project: TI_J7SVB_PCIE_ADD-ON-CARD; RoHS: RoHS; Temperature: -55°C+85°C; Tolerance: 20%; Voltage: 25V; Wattage: NA; Weight: 9.5mg; Datasheet: Y:\MIS_DATABASE\DATASHEETS\CAPACITORS\GRM21BR61E226ME44K.PDF
L6 = INDUCTOR: IND POWER 1.5uH 9.1A 20% SMD; Chkd/date: MANIRAJA/101019; Crtd /date: MANIRAJA/101019; Custom_Duty: 24%; Customs_HS_Code: 85437099; Distributor_name: MOUSER; Distributor_part_number: 994-XFL4020-152MEB; Footprint Path: Y:\MIS_DATABASE\Library\ALTIUM_TOOL\PCB_FOOTPRINTS\Altium_Footprint_Lib.PcbLib; Height: 2.10MM; Library Path: Y:\MIS_DATABASE\Library\ALTIUM_TOOL\SCHEMATICS_PARTS\MS_DISCRETE_Library.schlib; Mfr_name: COIL CRAFT; Mfr_part_number: XFL4020-152MEB; Mistral Part No: 130019100011-R; Package: SMD; Project: NPOL_UAIS_CONTROLLER-CARD; RoHS: RoHS; Temperature: -40°C+125°C; Tolerance: 20%; Voltage: NA; Wattage: NA; Weight: 169mg; Datasheet: Y:\MIS_DATABASE\DATASHEETS\DISCRETES\INDUCTORS\XFL4020.PDF
R206 = RESISTOR: RES 130K 1/10W 1% 0402; Chkd/date: MAZHAR/150611; Crtd /date: BAVISH/020611; Custom_Duty: 15%; Customs_HS_Code: 85332119; Distributor_name: DIGIKEY; Distributor_part_number: P130KLCT-ND; Footprint Path: Y:\MIS_DATABASE\Library\ALTIUM_TOOL\PCB_FOOTPRINTS\Altium_Footprint_Lib.PcbLib; Height: 0.40MM; Library Path: Y:\MIS_DATABASE\Library\ALTIUM_TOOL\SCHEMATICS_PARTS\MS_DISCRETE_Library.schlib; Mfr_name: PANASONIC-ECG; Mfr_part_number: ERJ-2RKF1303X; Mistral Part No: 110011060012-R; Package: 0402; Part_type: RESISTORS\FIXED; Project: AM4515_EVM_LCD; RoHS: RoHS; Temperature: -55°C+155°C; Tolerance: 1%; Voltage: NA; Wattage: 1/10W; Weight: 0.8mg; Datasheet: Y:\MIS_DATABASE\DATASHEETS\RESISTORS\PAN-ERJSER_NOV17.PDF
R209 = RESISTOR: RES 680K 1/10W 1% 0402; Chkd/date: SUHAS/200411; Crtd /date: MAZHAR/180411; Custom_Duty: 15%; Customs_HS_Code: 85332119; Distributor_name: DIGIKEY; Distributor_part_number: P680KLCT-ND; Footprint Path: Y:\MIS_DATABASE\Library\ALTIUM_TOOL\PCB_FOOTPRINTS\Altium_Footprint_Lib.PcbLib; Height: 0.40MM; Library Path: Y:\MIS_DATABASE\Library\ALTIUM_TOOL\SCHEMATICS_PARTS\MS_DISCRETE_Library.schlib; Mfr_name: PANASONIC-ECG; Mfr_part_number: ERJ-2RKF6803X; Mistral Part No: 110011040004-R; Package: 0402; Part_type: RESISTORS\FIXED; Project: AM4515_EVM_LCD; RoHS: RoHS; Temperature: -55°C+155°C; Tolerance: 1%; Voltage: NA; Wattage: 1/10W; Weight: 0.8mg; Datasheet: Y:\MIS_DATABASE\DATASHEETS\RESISTORS\PAN-ERJSER_NOV17.PDF
TP73 TP76 = TESTPOINT: TESTPOINT CIR 20 SMD; Chkd/date: SHREESHAIL/171006; Crtd /date: MAZHAR/171006; Custom_Duty: NA; Customs_HS_Code: NA; Distributor_name: NA; Distributor_part_number: NA; Footprint Path: Y:\MIS_DATABASE\Library\ALTIUM_TOOL\PCB_FOOTPRINTS\Altium_Footprint_Lib.PcbLib; Height: NA; Library Path: Y:\MIS_DATABASE\Library\ALTIUM_TOOL\SCHEMATICS_PARTS\MS_DISCRETE_Library.schlib; MECHANICAL 3D STEP FILE: NA; Mfr_name: LOCAL; Mistral Part No: NA; Package: SMD; Project: BT MODULE_CSRBC04; RoHS: NA; Temperature: NA; Tolerance: NA; Voltage: NA; Wattage: NA; Weight: NA; Datasheet: NA
U33 = TPS630701_VQFN-HR15: IC ADJ BUCK-BOOST CONVERTER WITH 3.6A SWITCH CURRENT VQFN-HR15; Chkd/date: ALVY/250122; Crtd /date: MANIRAJA/250122; Custom_Duty: 15%; Customs_HS_Code: 85423100; Distributor_name: DIGIKEY; Distributor_part_number: 296-TPS630702RNMRCT-ND; Footprint Path: Y:\MIS_DATABASE\Library\ALTIUM_TOOL\PCB_FOOTPRINTS\Altium_Footprint_Lib.PcbLib; Height: 1.00MM; Library Path: Y:\MIS_DATABASE\Library\ALTIUM_TOOL\SCHEMATICS_PARTS\MS_MISCPOWER_Library.schlib; Mfr_name: TEXAS INSTRUMENTS; Mistral Part No: 142022010015-R; Package: VQFN-HR15; Part_type: ICS\POWER\DC-DC CONVERTER; Project: AM62X_SKEVM; RoHS: RoHS; Temperature: -40°C+125°C; Tolerance: NA; Voltage: NA; Wattage: NA; Weight: 17.7mg; Datasheet: Y:\MIS_DATABASE\DATASHEETS\ICS\POWER\TPS630701X.PDF

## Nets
DGND: C120.2 C121.2 C122.2 C125.2 C127.2 C128.2 C129.1 C130.2 C131.1 C134.2 C136.2 C137.2 C138.2 C139.2 C142.2 C145.2 C146.2 C147.2 C148.2 C387.2 C393.2 C397.2 C401.2 C407.2 C414.2 C420.2 C421.2 C422.2 C423.2 C424.2 C534.2 C535.2 D5.2(ANODE) D10.2(ANODE) J13.A1(GND) J13.A12(GND) J13.B1(GND) J13.B12(GND) J23.2 J23.10 LD8.1(CATHODE) Q9.4(S1) Q9.7(S2) R159.2 R206.2 R437.1 R448.2 R454.2 R466.2 R478.2 R481.2 TP1.1(TP) TP11.1(TP) TP22.1(TP) TP32.1(TP) TP75.1(TP) TP92.1(TP) U30.4(GND) U33.4(GND) U33.10(PGND) U33.15(VSEL) U68.20(GND) U68.51(GND) U68.59(GND) U69.1(GND) U69.2(GND) U69.3(GND) U69.7(GND) ; also on sheet 1 2 3 4 15 16 17 18 19 20 21 22 23 24 25 26 27 28 29 30 31 32 33 34 35 36 37 38 39 40 41 42 43
VBUS_TYPEC1: C127.1 C393.1 C397.1 J13.A4(VBUS1) J13.A9(VBUS2) J13.B4(VBUS3) J13.B9(VBUS4) R165.1 U68.13(VBUS1) U69.4(IN1) U69.5(IN2) U69.6(IN3)
VBUS_TYPEC2: C134.1 C401.1 C407.1 C423.1 C424.1 C425.1 Q11.4(D1) Q11.7(D2) R484.1 U68.3(VBUS2) ; also on sheet 35 36
VCC_5V0: C144.1 C145.1 C146.1 C414.1 C420.1 C421.1 C534.1 C535.1 Q10.4(D1) Q10.7(D2) R202.2 R208.1 R209.1 R465.1 TP76.1(TP) U33.7(VOUT) ; also on sheet 33 35 38 41
VCC_5V0_FB: R206.1 R209.2 U33.5(FB)
VCC_5V0_PG: R202.1 U33.2(PG) ; also on sheet 42
ADCIN1: R452.2 R454.1 U68.6(ADCIN1)
ADCIN2: R448.1 R449.2 U68.10(ADCIN2)
DRAIN1: U68.8(DRAIN1_1) U68.15(DRAIN1_2) U68.19(DRAIN1_3) U68.58(DRAIN1_4)
DRAIN2: U68.7(DRAIN2_1) U68.52(DRAIN2_2) U68.56(DRAIN2_3) U68.57(DRAIN2_4)
LDO_1V8: C130.1 U68.35(LDO_1V8)
LDO_3V3: C122.1 C129.2 R158.1 R160.1 R161.1 R163.1 R164.1 R171.1 R436.1 R438.1 R439.1 R443.1 R449.1 R452.1 U30.8(VCC) U68.9(LDO_3V3)
P2_PP_EXT_ENABLE: R476.1 U68.49(GPIO17/PP_EXT2)
PD_GPIO0: R166.2 U68.16(GPIO0)
PD_HRESET: R466.1 U68.44(HRESET)
PD_M_I2C3_IRQ: R436.2 U68.23(~{I2C3_IRQ}/GPIO7)
PD_M_I2C3_SCL: R146.1 R164.2 U68.21(I2C3_SCL/GPIO5)
PD_M_I2C3_SDA: R150.1 R161.2 U68.22(I2C3_SDA/GPIO6)
PD_MS_I2C1_IRQ: R443.2 U68.29(~{I2C1_IRQ})
PD_MS_I2C1_SCL: R144.1 R439.2 U68.27(I2C1_SCL)
PD_MS_I2C1_SDA: R148.1 R438.2 U68.28(I2C1_SDA)
PD_S_I2C2_SCL: R446.2 U68.32(I2C2_SCL)
PD_S_I2C2_SDA: R447.2 U68.33(I2C2_SDA)
PD_SPI_CLK: J23.7 R461.2 U30.6(CLK)
PD_SPI_MISO: J23.5 R160.2 R453.2 U30.2(DO(IO1))
PD_SPI_MOSI: J23.8 R459.2 U30.5(DI(IO0))
PD_SPI_SS: J23.9 R158.2 R464.2 U30.1(~{CS})
PD_VIN_3V3: C131.2 U68.5(VIN_3V3)
PP1_CABLE: C125.1 U68.25(PP1_CABLE)
PP2_CABLE: R465.2 U68.46(PP2_CABLE)
SoC_I2C0_SCL: R446.1 ; also on sheet 4 23 32 33 37 42
SoC_I2C0_SDA: R447.1 ; also on sheet 4 23 32 33 37 42
SoC_USB0_DRVVBUS: R166.1 R475.1 ; also on sheet 35 36
SPI_HOLDn: R163.2 U30.7(~{HOLD}(IO3))
SPI_WPn: R171.2 U30.3(~{WP}(IO2))
TEST_POWERDOWN: R207.1 ; also on sheet 4 26 28
TPS630702_EN: R207.2 U33.14(EN) ; also on sheet 4
USB_TYPEC1_EARTH: C387.1 J13.SH1 J13.SH2 J13.SH3 J13.SH4 R159.1
USBC_CONN1_CC1: C121.1 D5.1(CATHODE) J13.A5(CC1) U68.24(C1_CC1)
USBC_CONN1_CC2: C120.1 D10.1(CATHODE) J13.B5(CC2) U68.26(C1_CC2)
USBC_CONN2_CC1: C139.1 U68.45(C2_CC1) ; also on sheet 36
USBC_CONN2_CC2: C138.1 U68.47(C2_CC2) ; also on sheet 36
VMAIN: C128.1 C136.1 C137.1 C147.1 C148.1 C422.1 R203.1 TP73.1(TP) U33.12(VIN) U68.1(PP_HV2) U68.11(PP_HV1) ; also on sheet 15 26
N17029933: LD8.2(ANODE) R165.2
N17370891: R437.2 U68.17(GPIO1)
N17827086: J23.1 R144.2 R146.2
N17827089: J23.3 R148.2 R150.2
N17849698: C143.1 Q10.1(S1) Q10.2(S2) Q10.5(S3) Q10.6(S4) Q10.8(S5) Q11.1(S1) Q11.2(S2) Q11.5(S3) Q11.6(S4) Q11.8(S5) R477.1
N17850096: C143.2 C144.2 C425.2 Q10.3(G) Q11.3(G) R208.2 R477.2 R482.1 R484.2
N17935978: Q9.3(G) R475.2 R476.2 R478.1
N17936309: Q9.1(D1) Q9.2(D2) Q9.5(D3) Q9.6(D4) Q9.8(D5) R482.2
N20506305: L6.1 U33.11(L1)
N20506307: L6.2 U33.9(L2)
N20506388: R481.1 U33.6(FB2)
N20506392: R203.2 U33.1(PS/SYNC)
N20506511: C142.1 U33.3(VAUX)
N21083676: R459.1 U68.37(SPI_MOSI/GPIO9)
N21083677: R453.1 U68.36(SPI_MISO/GPIO8)
N21083678: R464.1 U68.39(~{SPI_SS}/GPIO11)
N21083679: R461.1 U68.38(SPI_CLK/GPIO10)

Not connected (* = marked no-connect by the designer): J13 A2(TX1+)* A3(TX1-)* A6(D+_1)* A7(D-_1)* A8(SBU1)* A10(RX2-)* A11(RX2+)* B2(TX2+)* B3(TX2-)* B6(D+_2)* B7(D-_2)* B8(SBU2)* B10(RX1-)* B11(RX1+)*; J23 4* 6*; U68 18(GPIO2)* 30(HPD1/GPIO3)* 31(HPD2/GPIO4)* 34(~{I2C2_IRQ})* 40(GPIO12)* 41(GPIO13)* 42(GPIO14/PWM)* 43(GPIO15/PWM)* 48(GPIO16/PP_EXT1)* 50(C1_USB_P/GPIO18)* 53(C1_USB_N/GPIO19)* 54(C2_USB_P/GPIO20)* 55(C2_USB_N/GPIO21)*

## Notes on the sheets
sheet 13
- USB TYPE-C PD CONTROLLER AND POWER SUPPLY
- Silk: TYPE-C PWR
- TYPE-C DUAL PD CONTROLLER
- PD_VIN_3V3 is not connected
  anywhere TBD
- CAD NOTE:  Place Every Corner
  of the board One TP for Probing
  convenience
- POWER INDICATION LED: VBUS_TYPEC1
- D-Note:-
  Ok to use a 1K
  standard 5%
  tolerance resistor
- BP_NoWait
  Safe Configuration
- R-Note :-
  This is a supply
  negotiation indicator.
  On indicates success.
- EXTERNAL POWER PATH FOR SOURCING, 5V/0.5A
- I2C Slave
   Address
- Port1
- Port2
- I2C2(Default)
- 0x38
- 0x3F
- I2C1
- 0x20
- 0x24
- SPI EEPROM & PROGRAMMING HEADER
- $: R146TRI-PAD WITH R144
  R150TRI-PAD WITH R148
sheet 14
- PERIPHERAL POWER SUPPLIES - 1
- VinMin = 4.5V
  VinMax = 15V
  Vout = 5V @ 3.6A
- D-Note :-
  Add a Jumper or OR for isolation
  or Current measurement for
  preproduction board
- SILK SCREEN : VCC_5V0
- D-Note :-
  Power Cycle control from Test Automation
- PMIC ON
- PMIC OFF
